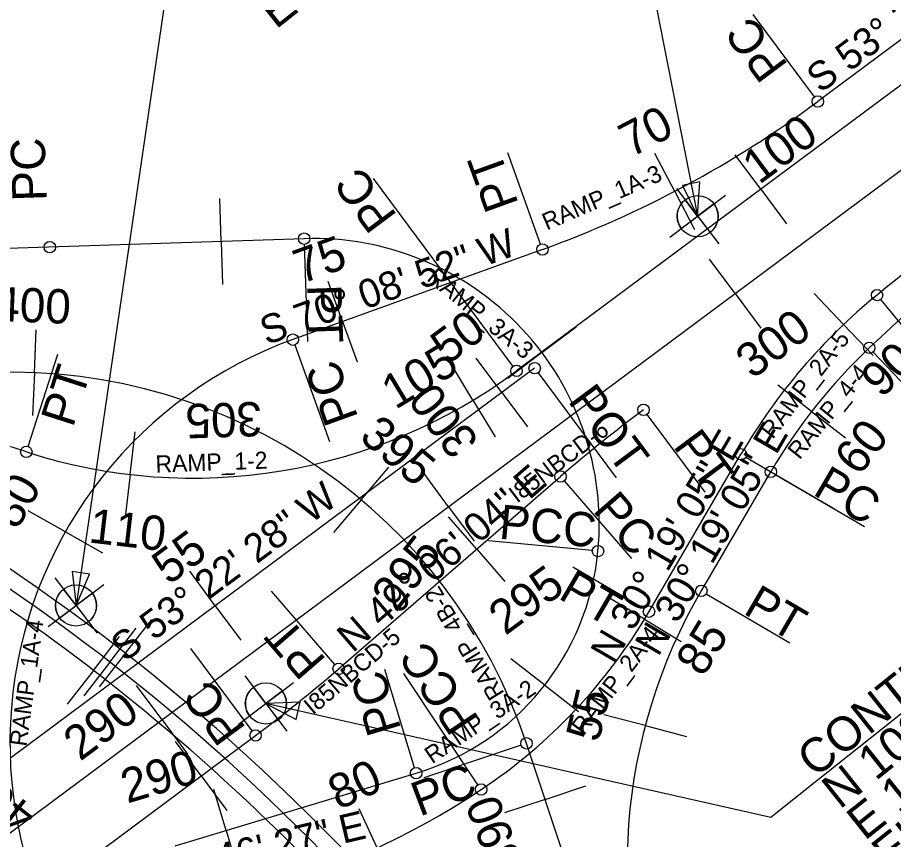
# Model space of a CAD drawing. Extents: x 1603447 to 1622636, y 1083818 to 1103958.
# Drawn here: x 1610566 to 1611793, y 1093718 to 1094869 of the extents above; entities that cross this region are included whole.
import ezdxf

# ---------------------------------------------------------------- set-up
doc = ezdxf.new("R2010")
doc.units = 0
for name, color, linetype in [('Level 1', 7, 'Continuous'), ('RD_HC_Points', 7, 'Continuous'), ('RD_HC_SUR_Bearing_TX400', 7, 'Continuous'), ('RD_HC_SUR_CL400', 7, 'Continuous'), ('RD_HC_SUR_PC_PT_400', 7, 'Continuous'), ('RD_HC_SUR_Tic400', 7, 'Continuous'), ('RD_HC_SUR_TX_Sta400', 7, 'Continuous'), ('RD_SHT_Misc1', 7, 'Continuous'), ('RD_TX_Misc1', 7, 'Continuous')]:
    doc.layers.add(name, color=color, linetype=linetype)

msp = doc.modelspace()

# ---------------------------------------------------------------- linework, layer by layer
at = {"layer": 'RD_HC_Points'}
msp.add_line((1612090.7, 1094122.5), (1611685.6, 1093800.2), dxfattribs=at)
for points in [[(1611473.4, 1095068.3), (1611431.1, 1095034.6), (1611518.8, 1094590.8)], [(1610826.1, 1094979.9), (1610780.2, 1094943.4), (1610648.2, 1094045.8)], [(1611685.6, 1093800.2), (1611621.4, 1093749.2), (1610914.1, 1093908.6)]]:
    msp.add_lwpolyline(points, dxfattribs=at)
for points in [[(1611497.6, 1094633.8), (1611518.8, 1094590.8), (1611522, 1094638.7)], [(1610642.6, 1094093.4), (1610648.2, 1094045.8), (1610667.2, 1094089.8)], [(1610962.1, 1093910.6), (1610914.1, 1093908.6), (1610956.6, 1093886.3)]]:
    msp.add_lwpolyline(points, close=True, dxfattribs=at)
at = {"layer": 'RD_HC_SUR_CL400'}
for p, q in [((1614436.6, 1096731.7), (1611265.2, 1094374.2)), ((1609261, 1092765), (1614429, 1096606.7)), ((1612058.8, 1095027.6), (1611687.1, 1094751.4)), ((1610967.7, 1094559.3), (1609851.2, 1094522)), ((1611301.6, 1094544.3), (1610951.8, 1094418)), ((1611290.5, 1094378), (1610191.6, 1093561.1)), ((1610578.6, 1094260.8), (1610318, 1094344.8)), ((1611450.7, 1094037.2), (1611579.5, 1094257.5)), ((1611016, 1093957.2), (1611326.7, 1094226.4)), ((1611524, 1094066.3), (1611621.4, 1094233)), ((1609780.9, 1093032.2), (1610899.7, 1093863.9)), ((1611399.8, 1093491), (1611279.1, 1093852.8)), ((1610787.1, 1093709.4), (1611124.6, 1093811))]:
    msp.add_line(p, q, dxfattribs=at)
for centre, radius, start, end in [((1615878.6, 1090044), 6000, 126.62559, 133.35895), ((1619021.1, 1085619), 11450, 126.62559, 129.29258), ((1610792.2, 1095955.2), 1500, 289.8521, 306.6256), ((1610981, 1094159.5), 400, 354.6184, 91.912), ((1612294.7, 1093839.2), 828.5, 129.2926, 149.6819), ((1611155.6, 1093853.7), 600, 109.8521, 236.724), ((1612294.7, 1093839.2), 780, 133.359, 149.6819), ((1609381.3, 1092295.5), 2102.7, 53.0731, 81.5065), ((1610558.2, 1093612.3), 760, 18.4471, 165.9491), ((1610811.8, 1094984.1), 760, 252.1319, 306.6256), ((1612636.2, 1092714.6), 2000, 126.6256, 130.899), ((1611020.8, 1094155.7), 360, 286.7519, 354.6184), ((1608910.9, 1091669.6), 2932.1, 37.9336, 56.1301), ((1608910.9, 1091669.6), 2908.8, 39.6334, 56.1301), ((1612180, 1093682.7), 760, 149.6819, 201.7343), ((1610794.7, 1094420.9), 760, 303.6278, 329.6819), ((1608910.9, 1091669.6), 2885.6, 39.6334, 53.0731), ((1609706.6, 1095469), 2000, 306.6256, 310.899), ((1610606.4, 1094704), 1100, 229.4294, 303.6278)]:
    msp.add_arc(centre, radius, start, end, dxfattribs=at)
at = {"layer": 'RD_HC_SUR_PC_PT_400'}
for p, q in [((1611682.4, 1094757.8), (1611596.6, 1094873.2)), ((1611298.9, 1094551.8), (1611252.8, 1094679.6)), ((1611260.5, 1094380.6), (1611064.9, 1094643.7)), ((1610967.9, 1094551.3), (1610972.5, 1094415.5)), ((1611775.1, 1094474.2), (1611893.8, 1094329.2)), ((1610954.5, 1094410.5), (1611003.3, 1094275.3)), ((1610581.1, 1094268.4), (1610622.8, 1094397.7)), ((1611764.7, 1094400.5), (1611893.4, 1094264.2)), ((1611295.3, 1094371.6), (1611404.7, 1094224.4)), ((1611447.8, 1094313.3), (1611528.8, 1094204.3)), ((1611586.4, 1094253.4), (1611710.5, 1094180.9)), ((1611628.3, 1094228.9), (1611752.4, 1094156.4)), ((1611331.9, 1094220.3), (1611426.1, 1094111.7)), ((1611371.3, 1094122.7), (1611226, 1094136.4)), ((1611443.8, 1094041.3), (1611344.1, 1094099.6)), ((1611010.8, 1093963.3), (1610921.8, 1094066)), ((1611530.9, 1094062.3), (1611648.1, 1093993.7)), ((1610894.9, 1093870.3), (1610809.2, 1093985.7)), ((1611122.3, 1093818.7), (1611080.9, 1093956.3)), ((1611211.1, 1093794.7), (1611107.3, 1093950.8)), ((1611271.5, 1093850.2), (1611135.2, 1093804.7))]:
    msp.add_line(p, q, dxfattribs=at)
for centre in [(1611687.1, 1094751.4), (1610967.7, 1094559.3), (1610611.4, 1094547.4), (1611301.6, 1094544.3), (1611770.1, 1094480.4), (1610951.8, 1094418), (1611759.2, 1094406.4), (1611265.2, 1094374.2), (1611290.5, 1094378), (1611443, 1094319.7), (1610578.6, 1094260.8), (1611579.5, 1094257.5), (1611326.7, 1094226.4), (1611621.4, 1094233), (1611379.3, 1094122), (1611524, 1094066.3), (1611450.7, 1094037.2), (1611016, 1093957.2), (1610899.7, 1093863.9), (1611279.1, 1093852.8), (1611124.6, 1093811), (1611215.6, 1093788.1)]:
    msp.add_circle(centre, 8, dxfattribs=at)
at = {"layer": 'RD_HC_SUR_Tic400'}
for p, q in [((1611737.8, 1094789), (1611737.8, 1094789)), ((1611767.8, 1094747.8), (1611767.8, 1094747.8)), ((1611657.3, 1094729.7), (1611657.3, 1094729.7)), ((1611687.6, 1094688.1), (1611687.6, 1094688.1)), ((1611486.7, 1094625.6), (1611458.9, 1094678.8)), ((1611607.3, 1094628.5), (1611571.5, 1094676.6)), ((1611573.7, 1094674.8), (1611573.7, 1094674.8)), ((1611607.3, 1094628.5), (1611643.1, 1094580.3)), ((1610851.5, 1094555.4), (1610849.5, 1094615.4)), ((1611486.7, 1094625.6), (1611514.4, 1094572.4)), ((1611731.8, 1094601.7), (1611731.8, 1094601.7)), ((1611396.6, 1094582.3), (1611396.6, 1094582.3)), ((1611527.1, 1094568.8), (1611527.1, 1094568.8)), ((1610851.5, 1094555.4), (1610853.5, 1094495.4)), ((1610951.5, 1094558.7), (1610951.5, 1094558.7)), ((1610951.5, 1094558.7), (1610951.5, 1094558.7)), ((1611051.1, 1094553.3), (1611051.1, 1094553.3)), ((1611051.1, 1094553.3), (1611051.1, 1094553.3)), ((1610651.6, 1094548.7), (1610651.6, 1094548.7)), ((1610651.6, 1094548.7), (1610651.6, 1094548.7)), ((1610751.6, 1094552.1), (1610751.6, 1094552.1)), ((1610751.6, 1094552.1), (1610751.6, 1094552.1)), ((1611303.8, 1094545.1), (1611303.8, 1094545.1)), ((1611651.5, 1094542), (1611651.5, 1094542)), ((1611571.3, 1094482.4), (1611535.5, 1094530.5)), ((1611146.3, 1094523.7), (1611146.3, 1094523.7)), ((1611146.3, 1094523.7), (1611146.3, 1094523.7)), ((1611209.7, 1094511.1), (1611209.7, 1094511.1)), ((1611446.8, 1094509.2), (1611446.8, 1094509.2)), ((1611021.6, 1094443.2), (1611001.2, 1094499.6)), ((1611571.3, 1094482.4), (1611607.1, 1094434.2)), ((1611723.3, 1094439.1), (1611681.9, 1094482.5)), ((1611115.6, 1094477.2), (1611115.6, 1094477.2)), ((1611231.3, 1094471.5), (1611231.3, 1094471.5)), ((1611231.3, 1094471.5), (1611231.3, 1094471.5)), ((1611021.6, 1094443.2), (1611042, 1094386.8)), ((1611366.6, 1094449.5), (1611366.6, 1094449.5)), ((1610589.9, 1094371.6), (1610592.4, 1094431.6)), ((1611300.7, 1094399.9), (1611348.7, 1094435.9)), ((1611300.7, 1094399.9), (1611348.7, 1094435.9)), ((1611723.3, 1094439.1), (1611764.6, 1094395.7)), ((1611491, 1094422.7), (1611491, 1094422.7)), ((1610927.7, 1094408.7), (1610927.7, 1094408.7)), ((1611300.7, 1094399.9), (1611252.8, 1094363.8)), ((1611300.7, 1094399.9), (1611252.8, 1094363.8)), ((1611204, 1094333.1), (1611173, 1094384.5)), ((1611244.5, 1094343.8), (1611208.7, 1094392)), ((1611286.3, 1094389.9), (1611286.3, 1094389.9)), ((1611744.6, 1094392.2), (1611744.6, 1094392.2)), ((1611744.6, 1094392.2), (1611744.6, 1094392.2)), ((1610589.9, 1094371.6), (1610587.4, 1094311.7)), ((1610689.3, 1094360.9), (1610689.3, 1094360.9)), ((1610838.8, 1094363.2), (1610838.8, 1094363.2)), ((1611410.8, 1094363.1), (1611410.8, 1094363.1)), ((1611655.2, 1094365.9), (1611655.2, 1094365.9)), ((1611678.4, 1094317.3), (1611631, 1094354.1)), ((1610786.4, 1094337.2), (1610786.4, 1094337.2)), ((1611204, 1094333.1), (1611235, 1094281.7)), ((1611244.5, 1094343.8), (1611280.3, 1094295.7)), ((1611350.3, 1094313.3), (1611350.3, 1094313.3)), ((1611350.3, 1094313.3), (1611350.3, 1094313.3)), ((1611439.5, 1094317.1), (1611439.5, 1094317.1)), ((1611678.4, 1094317.3), (1611725.8, 1094280.5)), ((1610758.7, 1094303.6), (1610758.7, 1094303.6)), ((1610879.5, 1094301), (1610879.5, 1094301)), ((1611330.5, 1094303.4), (1611330.5, 1094303.4)), ((1610724.1, 1094229.2), (1610731, 1094288.8)), ((1611115.2, 1094287.3), (1611115.2, 1094287.3)), ((1611164.3, 1094284.2), (1611164.3, 1094284.2)), ((1611596.4, 1094285.1), (1611596.4, 1094285.1)), ((1610625.8, 1094247.2), (1610625.8, 1094247.2)), ((1610967.1, 1094252.9), (1610967.1, 1094252.9)), ((1611021.2, 1094253.5), (1611021.2, 1094253.5)), ((1611360.9, 1094255.3), (1611360.9, 1094255.3)), ((1611047.6, 1094193.7), (1611086.2, 1094239.6)), ((1611250.3, 1094243.8), (1611250.3, 1094243.8)), ((1611622.4, 1094234.6), (1611622.4, 1094234.6)), ((1611622.4, 1094234.6), (1611622.4, 1094234.6)), ((1610689.5, 1094231.5), (1610689.5, 1094231.5)), ((1610724.1, 1094229.2), (1610717.2, 1094169.6)), ((1610823.9, 1094224.2), (1610823.9, 1094224.2)), ((1610923.5, 1094232.4), (1610923.5, 1094232.4)), ((1611084, 1094224.5), (1611084, 1094224.5)), ((1611170, 1094184.1), (1611134.2, 1094232.3)), ((1611376.8, 1094217.2), (1611376.8, 1094217.2)), ((1611376.8, 1094217.2), (1611376.8, 1094217.2)), ((1611545.4, 1094199.1), (1611545.4, 1094199.1)), ((1611047.6, 1094193.7), (1611009, 1094147.8)), ((1611285, 1094190.2), (1611285, 1094190.2)), ((1610633.3, 1094149), (1610581, 1094178.5)), ((1611170, 1094184.1), (1611205.8, 1094135.9)), ((1611003.8, 1094164.9), (1611003.8, 1094164.9)), ((1611209.4, 1094124.7), (1611170.1, 1094170.1)), ((1610633.3, 1094149), (1610685.5, 1094119.5)), ((1611571.9, 1094148.3), (1611571.9, 1094148.3)), ((1611571.9, 1094148.3), (1611571.9, 1094148.3)), ((1611089.8, 1094124.4), (1611089.8, 1094124.4)), ((1611119.6, 1094124.5), (1611119.6, 1094124.5)), ((1611209.4, 1094124.7), (1611248.7, 1094079.4)), ((1611378.8, 1094117.4), (1611378.8, 1094117.4)), ((1611378.8, 1094117.4), (1611378.8, 1094117.4)), ((1611494.9, 1094112.8), (1611494.9, 1094112.8)), ((1610923.5, 1094105.2), (1610923.5, 1094105.2)), ((1610843.2, 1094045.5), (1610807.4, 1094093.7)), ((1611009.5, 1094064.8), (1611009.5, 1094064.8)), ((1610591.5, 1094058.3), (1610591.5, 1094058.3)), ((1611133.8, 1094059.3), (1611133.8, 1094059.3)), ((1611444.4, 1094026.5), (1611393.1, 1094057.6)), ((1611521.4, 1094061.9), (1611521.4, 1094061.9)), ((1610637.7, 1094039.2), (1610637.7, 1094039.2)), ((1610843.2, 1094045.5), (1610879, 1093997.4)), ((1611182, 1094046.4), (1611182, 1094046.4)), ((1610615.7, 1094026.5), (1610615.7, 1094026.5)), ((1610717.5, 1093979), (1610754.5, 1094026.2)), ((1611444.4, 1094026.5), (1611495.6, 1093995.4)), ((1610592.2, 1094014.4), (1610592.2, 1094014.4)), ((1610695.7, 1093966.5), (1610732.5, 1094013.9)), ((1611354.6, 1094020.8), (1611354.6, 1094020.8)), ((1611356, 1094020.3), (1611356, 1094020.3)), ((1610672.6, 1093955), (1610709.2, 1094002.5)), ((1610929.2, 1094005.1), (1610929.2, 1094005.1)), ((1611058.2, 1093993.8), (1611058.2, 1093993.8)), ((1610717.5, 1093979), (1610680.5, 1093931.7)), ((1610763, 1093985.9), (1610763, 1093985.9)), ((1610695.7, 1093966.5), (1610658.9, 1093919.2)), ((1611304.8, 1093934.4), (1611257.4, 1093971.3)), ((1611477.3, 1093972.3), (1611477.3, 1093972.3)), ((1610672.6, 1093955), (1610635.9, 1093907.5)), ((1611233.6, 1093960.8), (1611233.6, 1093960.8)), ((1610849, 1093945.5), (1610849, 1093945.5)), ((1611387, 1093944.7), (1611387, 1093944.7)), ((1610768.7, 1093885.8), (1610732.9, 1093934)), ((1610982.3, 1093928.7), (1610982.3, 1093928.7)), ((1611304.8, 1093934.4), (1611352.1, 1093897.5)), ((1610682.7, 1093926.2), (1610682.7, 1093926.2)), ((1610795.2, 1093916), (1610795.2, 1093916)), ((1610773.6, 1093903.8), (1610773.6, 1093903.8)), ((1610750.7, 1093892.6), (1610750.7, 1093892.6)), ((1611445.4, 1093877.6), (1611387.4, 1093892.9)), ((1610768.7, 1093885.8), (1610804.5, 1093837.7)), ((1610602.5, 1093866.6), (1610602.5, 1093866.6)), ((1610903.7, 1093866.9), (1610903.7, 1093866.9)), ((1611273.5, 1093869.2), (1611273.5, 1093869.2)), ((1611319.4, 1093871.1), (1611319.4, 1093871.1)), ((1611445.4, 1093877.6), (1611503.4, 1093862.2)), ((1610823.5, 1093807.2), (1610787.7, 1093855.3)), ((1611233.2, 1093865), (1611233.2, 1093865)), ((1611243.4, 1093857.6), (1611243.4, 1093857.6)), ((1610870.7, 1093850.5), (1610870.7, 1093850.5)), ((1610849.3, 1093838.5), (1610849.3, 1093838.5)), ((1610688.5, 1093826.1), (1610688.5, 1093826.1)), ((1610826.6, 1093827.5), (1610826.6, 1093827.5)), ((1611145.3, 1093817.9), (1611145.3, 1093817.9)), ((1610823.5, 1093807.2), (1610859.3, 1093759)), ((1611242.7, 1093807), (1611242.7, 1093807)), ((1611160.6, 1093802), (1611160.6, 1093802)), ((1611305.3, 1093774.4), (1611362.2, 1093793.4)), ((1610858.3, 1093730.8), (1610841, 1093788.3)), ((1610943.9, 1093782.4), (1610943.9, 1093782.4)), ((1611049.8, 1093788.5), (1611049.8, 1093788.5)), ((1610922.7, 1093770.6), (1610922.7, 1093770.6)), ((1611305.3, 1093774.4), (1611248.4, 1093755.4)), ((1611426.2, 1093779.5), (1611426.2, 1093779.5)), ((1610608.2, 1093766.5), (1610608.2, 1093766.5)), ((1610900.2, 1093759.8), (1610900.2, 1093759.8)), ((1610954, 1093759.7), (1610954, 1093759.7)), ((1611070.1, 1093706.5), (1611044.8, 1093760.9)), ((1610743.2, 1093747.5), (1610743.2, 1093747.5)), ((1611158.8, 1093752.7), (1611158.8, 1093752.7)), ((1610858.3, 1093730.8), (1610875.6, 1093673.4))]:
    msp.add_line(p, q, dxfattribs=at)
at = {"layer": 'RD_SHT_Misc1'}
for p, q in [((1611489.3, 1094629.6), (1611548.3, 1094552)), ((1611480, 1094561.3), (1611557.6, 1094620.3)), ((1611518.8, 1094590.8), (1611501.4, 1094613.6)), ((1611541.7, 1094608.2), (1611518.8, 1094590.8)), ((1611495.9, 1094573.4), (1611518.8, 1094590.8)), ((1611518.8, 1094590.8), (1611536.2, 1094567.9)), ((1610609.4, 1094016.2), (1610687, 1094075.3)), ((1610618.7, 1094084.6), (1610677.7, 1094006.9)), ((1610648.2, 1094045.8), (1610630.8, 1094068.6)), ((1610671.1, 1094063.2), (1610648.2, 1094045.8)), ((1610625.3, 1094028.4), (1610648.2, 1094045.8)), ((1610648.2, 1094045.8), (1610665.6, 1094022.9)), ((1610884.6, 1093947.4), (1610943.6, 1093869.8)), ((1610875.3, 1093879.1), (1610952.9, 1093938.1)), ((1610914.1, 1093908.6), (1610896.7, 1093931.5)), ((1610937, 1093926), (1610914.1, 1093908.6)), ((1610891.2, 1093891.2), (1610914.1, 1093908.6)), ((1610914.1, 1093908.6), (1610931.5, 1093885.8))]:
    msp.add_line(p, q, dxfattribs=at)
for centre in [(1611518.8, 1094590.8), (1610648.2, 1094045.8), (1610914.1, 1093908.6)]:
    msp.add_circle(centre, 28.8, dxfattribs=at)
for centre, start, end in [((1611518.8, 1094590.8), 127.2464, 217.2464), ((1611518.8, 1094590.8), 307.2464, 37.2464), ((1610648.2, 1094045.8), 127.2464, 217.2464), ((1610648.2, 1094045.8), 307.2464, 37.2464), ((1610914.1, 1093908.6), 127.2464, 217.2464), ((1610914.1, 1093908.6), 307.2464, 37.2464)]:
    msp.add_arc(centre, 28.8, start, end, dxfattribs=at)

# ---------------------------------------------------------------- texts
at = {"layer": 'Level 1'}
for s, rotation, p in [('75', 19.8521, (1610963.7, 1094495.7)), ('105', 31.0666, (1611095.4, 1094319.3)), ('305', 181.912, (1610907.8, 1094331.1)), ('395', 319.9127, (1611043.2, 1094279)), ('55', 36.6256, (1610778, 1094073.4)), ('295', 52.0627, (1611096.5, 1094034.9)), ('295', 36.6256, (1611249.5, 1094002.9)), ('85', 58.7409, (1611526.7, 1093944.2)), ('55', 76.5611, (1611380.3, 1093852.9))]:
    msp.add_text(s, height=48, rotation=rotation, dxfattribs=at).set_placement(p)
at = {"layer": 'RD_HC_Points'}
for s, p in [('EL = 1025.02', (1610928.2, 1094851.6)), ('CONTROL L2-209', (1611683.1, 1093803.4)), ('N 1093908.6381', (1611717.9, 1093759.5)), ('E 1610914.1339', (1611752.8, 1093715.7)), ('EL = 992.75', (1611787.7, 1093671.9))]:
    msp.add_text(s, height=48, rotation=38.4995, dxfattribs=at).set_placement(p)
at = {"layer": 'RD_HC_SUR_Bearing_TX400'}
for s, rotation, p in [('S 53%%d 22\' 28" W', 36.6256, (1611690.7, 1094762.1)), ('S 70%%d 08\' 52" W', 19.8521, (1610914.9, 1094410)), ('N 30%%d 19\' 05" E', 59.6819, (1611463.5, 1093972.9)), ('N 30%%d 19\' 05" E', 59.6819, (1611401.2, 1093962.4)), ('N 49%%d 06\' 04" E', 40.899, (1611035.7, 1093978.4)), ('S 53%%d 22\' 28" W', 36.6256, (1610716.3, 1093965.7)), ('N 76%%d 46\' 27" E', 13.2258, (1610703.5, 1093637.2))]:
    msp.add_text(s, height=40, rotation=rotation, dxfattribs=at).set_placement(p)
at = {"layer": 'RD_HC_SUR_PC_PT_400'}
for s, rotation, p in [('PC', 126.6256, (1611646.7, 1094802.3)), ('PC', 91.912, (1610607.2, 1094612.3)), ('PT', 109.8521, (1611268.5, 1094608.1)), ('PC', 126.6256, (1611099.1, 1094591.5)), ('PT', 271.912, (1610971.8, 1094494.4)), ('PT', 72.1319, (1610643.7, 1094293.7)), ('PC', 109.8521, (1611043.9, 1094308.9)), ('POT', 306.6256, (1611336, 1094332)), ('PT', 306.6256, (1611483.4, 1094268.8)), ('PC', 329.6819, (1611678.5, 1094201.9)), ('PC', 329.6819, (1611678.5, 1094201.9)), ('PC', 310.899, (1611370.8, 1094178.5)), ('PCC', 354.6184, (1611239.6, 1094139.5)), ('PT', 329.6819, (1611322.1, 1094056.6)), ('PT', 329.6819, (1611581.1, 1094035.3)), ('PT', 130.899, (1611000, 1093969.6)), ('PCC', 123.6278, (1611213.6, 1093886.7)), ('PC', 106.7519, (1611104, 1093872.7)), ('PC', 126.6256, (1610887.4, 1093873.9)), ('PC', 20.7167, (1611129.4, 1093749.9))]:
    msp.add_text(s, height=48, rotation=rotation, dxfattribs=at).set_placement(p)
at = {"layer": 'RD_HC_SUR_TX_Sta400'}
for s, rotation, p in [('70', 27.5776, (1611425.2, 1094672.3)), ('100', 36.6256, (1611605, 1094634.2)), ('400', 357.6073, (1610532.9, 1094444.4)), ('50', 36.6256, (1611168.3, 1094381.7)), ('300', 36.6256, (1611595.6, 1094361.7)), ('90', 43.6117, (1611776.2, 1094334.9)), ('300', 126.938, (1611214.1, 1094276.2)), ('60', 52.1988, (1611745, 1094225.5)), ('80', 60.5147, (1610565.7, 1094150.2)), ('110', 353.372, (1610664.8, 1094134.2)), ('290', 36.6256, (1610654, 1093826.9)), ('290', 16.7519, (1610719.8, 1093768.3)), ('400', 142.1517, (1610595.7, 1093758)), ('80', 24.9351, (1611015.9, 1093758.9)), ('390', 110.7167, (1611275.5, 1093684.1))]:
    msp.add_text(s, height=48, rotation=rotation, dxfattribs=at).set_placement(p)
at = {"layer": 'RD_TX_Misc1'}
for s, rotation, p in [('RAMP_1A-3', 23.4981, (1611307.6, 1094570.5)), ('RAMP_3A-3', 320.7997, (1611138.1, 1094501.9)), ('RAMP_2A-5', 52.304, (1611624, 1094277.6)), ('RAMP_4-4', 51.0597, (1611661.4, 1094248.8)), ('I85NBCD-6', 37.0697, (1611265.8, 1094188.3)), ('RAMP_1-2', 2.1024, (1610759.9, 1094231.7)), ('RAMP_4B-2', 121.4244, (1611248.8, 1093922.8)), ('RAMP_1A-4', 82.2275, (1610578.7, 1093847.6)), ('I85NBCD-5', 40.4832, (1610980, 1093891.6)), ('RAMP_2A-4', 52.8643, (1611359.4, 1093862.9)), ('RAMP_3A-2', 34.2826, (1611147, 1093823.3))]:
    msp.add_text(s, height=24, rotation=rotation, dxfattribs=at).set_placement(p)

doc.saveas('drawing.dxf')
